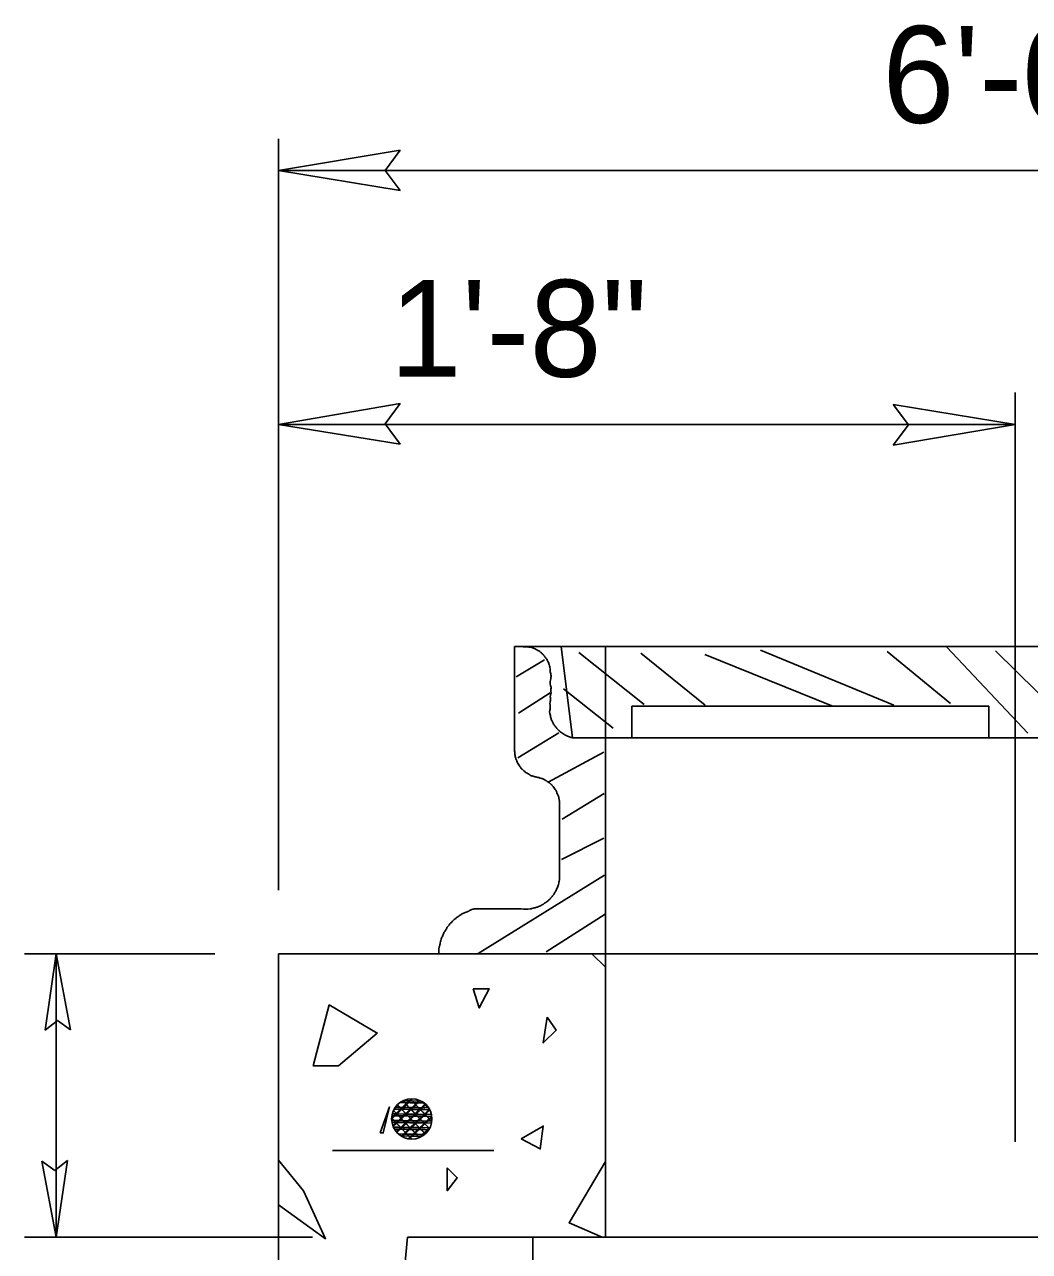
# Model space of a CAD drawing. Extents: x 26.41 to 33.74, y 20.66 to 30.6.
# Drawn here: x 31.629 to 32.251, y 27.649 to 28.409 of the extents above; entities that cross this region are included whole.
import ezdxf

# ---------------------------------------------------------------- set-up
doc = ezdxf.new("R2010")
doc.units = 0
for name, color, linetype in [('DETL-DIMS', 7, 'Continuous'), ('DETL-LINE', 7, 'Continuous'), ('DETL-NOTE', 7, 'Continuous'), ('DETL-PATT', 7, 'Continuous')]:
    doc.layers.add(name, color=color, linetype=linetype)

msp = doc.modelspace()

# ---------------------------------------------------------------- linework, layer by layer
at = {"layer": 'DETL-DIMS'}
for p, q in [((31.7863, 27.87307), (31.7863, 28.33841)), ((31.86177, 28.33142), (31.7863, 28.31876)), ((31.86177, 28.33142), (31.85234, 28.31884)), ((31.86177, 28.30626), (31.7863, 28.31876)), ((31.7863, 28.31876), (33.34406, 28.31876)), ((31.86177, 28.30626), (31.85234, 28.31884)), ((32.24248, 27.71735), (32.24248, 28.18119)), ((31.86173, 28.17447), (31.7863, 28.16154)), ((31.86173, 28.17447), (31.85234, 28.16185)), ((32.16698, 28.17376), (32.24248, 28.16154)), ((32.16698, 28.17376), (32.17645, 28.16122)), ((31.86181, 28.14931), (31.7863, 28.16154)), ((31.7863, 28.16154), (32.24248, 28.16154)), ((31.86181, 28.14931), (31.85234, 28.16185)), ((32.16706, 28.14861), (32.24248, 28.16154)), ((32.16706, 28.14861), (32.17645, 28.16122)), ((31.747, 27.83377), (31.62908, 27.83377)), ((31.64185, 27.78644), (31.64873, 27.83377)), ((31.65758, 27.78676), (31.64873, 27.83377)), ((31.64873, 27.65839), (31.64873, 27.83377)), ((31.64185, 27.78644), (31.64956, 27.7925)), ((31.65758, 27.78676), (31.64956, 27.7925)), ((31.63989, 27.7054), (31.64873, 27.65839)), ((31.63989, 27.7054), (31.64791, 27.69966)), ((31.65561, 27.70571), (31.64791, 27.69966)), ((31.65561, 27.70571), (31.64873, 27.65839)), ((31.80737, 27.65839), (31.62908, 27.65839))]:
    msp.add_line(p, q, dxfattribs=at)
at = {"layer": 'DETL-LINE'}
for p, q in [((32.55233, 28.02397), (31.9326, 28.02397)), ((31.9326, 27.968), (31.9326, 28.02397)), ((31.96848, 27.96753), (31.96133, 28.02397)), ((31.98881, 27.65839), (31.98881, 28.02397)), ((32.0052, 27.98718), (32.0052, 27.96753)), ((32.22629, 27.98718), (32.0052, 27.98718)), ((32.22629, 27.98718), (32.22629, 27.96753)), ((32.51641, 27.96753), (31.96848, 27.96753)), ((31.96047, 27.92622), (31.96047, 27.88094)), ((31.7863, 27.83377), (31.7863, 27.25786)), ((33.34406, 27.83377), (31.7863, 27.83377)), ((31.88579, 27.83377), (32.59918, 27.83377)), ((31.86806, 27.74341), (31.85855, 27.73425)), ((31.86853, 27.74313), (31.85898, 27.73397)), ((31.85819, 27.73613), (31.86735, 27.72658)), ((31.86798, 27.73759), (31.85843, 27.72839)), ((31.86841, 27.73727), (31.8589, 27.72812)), ((31.87278, 27.7344), (31.85953, 27.73464)), ((31.87281, 27.73735), (31.85957, 27.73759)), ((31.87285, 27.73853), (31.85961, 27.73877)), ((31.86114, 27.73896), (31.87034, 27.72945)), ((31.87085, 27.73464), (31.8613, 27.72544)), ((31.87093, 27.74046), (31.86142, 27.73126)), ((31.8714, 27.74014), (31.86185, 27.73098)), ((31.87694, 27.73727), (31.8637, 27.73751)), ((31.87698, 27.73845), (31.86374, 27.73869)), ((31.86401, 27.73602), (31.87321, 27.72646)), ((31.86413, 27.74183), (31.87329, 27.73232)), ((31.8738, 27.73751), (31.86429, 27.72827)), ((31.87427, 27.73719), (31.86468, 27.728)), ((31.86696, 27.73885), (31.87616, 27.72933)), ((31.87678, 27.74038), (31.86727, 27.73114)), ((31.87722, 27.74006), (31.86767, 27.73087)), ((31.86983, 27.73594), (31.87903, 27.72635)), ((31.86995, 27.74171), (31.87914, 27.7322)), ((31.87965, 27.73739), (31.8701, 27.72819)), ((31.88005, 27.73708), (31.87054, 27.72788)), ((31.85808, 27.73028), (31.86723, 27.72076)), ((31.87266, 27.7291), (31.85941, 27.72933)), ((31.8727, 27.73028), (31.85945, 27.73051)), ((31.87274, 27.73322), (31.85949, 27.73346)), ((31.86106, 27.73315), (31.87022, 27.72359)), ((31.87128, 27.73433), (31.86177, 27.72513)), ((31.87678, 27.72902), (31.86354, 27.72925)), ((31.87682, 27.7302), (31.86358, 27.73043)), ((31.87686, 27.73315), (31.86362, 27.73338)), ((31.8769, 27.73433), (31.86366, 27.73456)), ((31.86389, 27.7302), (31.87309, 27.72065)), ((31.87372, 27.73165), (31.86417, 27.72249)), ((31.87415, 27.73134), (31.8646, 27.72214)), ((31.86684, 27.73307), (31.87608, 27.72348)), ((31.87659, 27.72867), (31.86704, 27.71951)), ((31.87667, 27.73452), (31.86715, 27.72532)), ((31.87698, 27.72839), (31.86747, 27.71919)), ((31.8771, 27.73421), (31.86755, 27.72501)), ((31.88091, 27.72894), (31.86767, 27.72918)), ((31.88095, 27.73012), (31.86771, 27.73036)), ((31.88099, 27.73307), (31.86774, 27.7333)), ((31.88103, 27.73425), (31.86778, 27.73448)), ((31.87954, 27.73153), (31.86998, 27.72238)), ((31.87997, 27.73122), (31.87042, 27.72206)), ((31.87258, 27.72497), (31.85933, 27.72521)), ((31.87262, 27.72615), (31.85937, 27.72639)), ((31.87667, 27.72194), (31.86342, 27.72218)), ((31.87671, 27.72489), (31.86346, 27.72513)), ((31.87675, 27.72607), (31.8635, 27.72631)), ((31.91967, 27.71188), (31.81983, 27.71188)), ((31.85811, 27.57172), (31.86633, 27.65839)), ((31.86633, 27.65839), (33.24596, 27.65839)), ((31.94396, 27.25786), (31.94396, 27.65839))]:
    msp.add_line(p, q, dxfattribs=at)
for points in [[(31.86869, 27.74399), (31.86153, 27.73712)], [(31.8694, 27.74399), (31.86197, 27.7368)], [(31.8633, 27.7427), (31.87046, 27.73531)], [(31.87289, 27.74262), (31.86358, 27.74282)], [(31.86881, 27.7427), (31.86358, 27.74282)], [(31.86468, 27.74278), (31.86358, 27.74282)], [(31.8747, 27.74262), (31.86381, 27.74282)], [(31.87364, 27.74309), (31.8644, 27.73413)], [(31.86869, 27.74399), (31.86452, 27.73999)], [(31.87419, 27.74285), (31.8648, 27.73385)], [(31.8694, 27.74399), (31.86491, 27.73967)], [(31.87364, 27.74309), (31.86739, 27.737)], [(31.87419, 27.74285), (31.86778, 27.73668)], [(31.86782, 27.74396), (31.8734, 27.73814)], [(31.86782, 27.74396), (31.87627, 27.73519)], [(31.8747, 27.74262), (31.86794, 27.74274)], [(31.8747, 27.74262), (31.87207, 27.74266)], [(31.87502, 27.74246), (31.87639, 27.74101)], [(31.87502, 27.74246), (31.87926, 27.73806)], [(31.87502, 27.74246), (31.88009, 27.73719)], [(31.86554, 27.74026), (31.85646, 27.73153)], [(31.86256, 27.73739), (31.85646, 27.73153)], [(31.86511, 27.74058), (31.8565, 27.73224)], [(31.86212, 27.73771), (31.8565, 27.73224)], [(31.85918, 27.73484), (31.8565, 27.73224)], [(31.86865, 27.73448), (31.8569, 27.73468)], [(31.86452, 27.73452), (31.8569, 27.73468)], [(31.86039, 27.7346), (31.8569, 27.73468)], [(31.86499, 27.73472), (31.85721, 27.72725)], [(31.8576, 27.73672), (31.86448, 27.72957)], [(31.86869, 27.73743), (31.85808, 27.73763)], [(31.86456, 27.73751), (31.85808, 27.73763)], [(31.86043, 27.73759), (31.85808, 27.73763)], [(31.86873, 27.73857), (31.85878, 27.73877)], [(31.8646, 27.73865), (31.85878, 27.73877)], [(31.86047, 27.73873), (31.85878, 27.73877)], [(31.85996, 27.74018), (31.86747, 27.73244)], [(31.87289, 27.74148), (31.86169, 27.74168)], [(31.86877, 27.74156), (31.86169, 27.74168)], [(31.86464, 27.74164), (31.86169, 27.74168)], [(31.87655, 27.7414), (31.86377, 27.74164)], [(31.88005, 27.73719), (31.86782, 27.73743)], [(31.87934, 27.73837), (31.86786, 27.73861)], [(31.87655, 27.7414), (31.8679, 27.74156)], [(31.87726, 27.74081), (31.87022, 27.73401)], [(31.87765, 27.7405), (31.87065, 27.73374)], [(31.88005, 27.73719), (31.87195, 27.73735)], [(31.87934, 27.73837), (31.87199, 27.73853)], [(31.87655, 27.7414), (31.87203, 27.74148)], [(31.87281, 27.73877), (31.88127, 27.72996)], [(31.87985, 27.73755), (31.87309, 27.73106)], [(31.88009, 27.73712), (31.87352, 27.73075)], [(31.87568, 27.73582), (31.88127, 27.72996)], [(31.8758, 27.74164), (31.88009, 27.73719)], [(31.87863, 27.73865), (31.88009, 27.73719)], [(31.85961, 27.73452), (31.85646, 27.73153)], [(31.85646, 27.73193), (31.86149, 27.7267)], [(31.85646, 27.73193), (31.86436, 27.72371)], [(31.85662, 27.73165), (31.85646, 27.73153)], [(31.86857, 27.73036), (31.8565, 27.73055)], [(31.86444, 27.73043), (31.8565, 27.73055)], [(31.86032, 27.73047), (31.8565, 27.73055)], [(31.86861, 27.7333), (31.85666, 27.7335)], [(31.86448, 27.73338), (31.85666, 27.7335)], [(31.86035, 27.73346), (31.85666, 27.7335)], [(31.86853, 27.72918), (31.85666, 27.72937)], [(31.8644, 27.72925), (31.85666, 27.72937)], [(31.86028, 27.72933), (31.85666, 27.72937)], [(31.86201, 27.73189), (31.85721, 27.72725)], [(31.85906, 27.72902), (31.85721, 27.72725)], [(31.86543, 27.7344), (31.85745, 27.72674)], [(31.86248, 27.73153), (31.85745, 27.72674)], [(31.85949, 27.7287), (31.85745, 27.72674)], [(31.86786, 27.73177), (31.85933, 27.72356)], [(31.86488, 27.7289), (31.85933, 27.72356)], [(31.86829, 27.73146), (31.85969, 27.72316)], [(31.86531, 27.72863), (31.85969, 27.72316)], [(31.86094, 27.72733), (31.86884, 27.71907)], [(31.87073, 27.72878), (31.86252, 27.72084)], [(31.87116, 27.72851), (31.86299, 27.72061)], [(31.86676, 27.72721), (31.87368, 27.72002)], [(31.86971, 27.73008), (31.87726, 27.72226)], [(31.88111, 27.72894), (31.87179, 27.7291)], [(31.8813, 27.73012), (31.87183, 27.73028)], [(31.8813, 27.73307), (31.87187, 27.73322)], [(31.88111, 27.73425), (31.87191, 27.7344)], [(31.87258, 27.72709), (31.87726, 27.72226)], [(31.8727, 27.73295), (31.87985, 27.72552)], [(31.88127, 27.73319), (31.87297, 27.72525)], [(31.88134, 27.73256), (31.8734, 27.72493)], [(31.87557, 27.72996), (31.87985, 27.72552)], [(31.88127, 27.73319), (31.87596, 27.72808)], [(31.88134, 27.73256), (31.87639, 27.7278)], [(31.87855, 27.73283), (31.88127, 27.72996)], [(31.86849, 27.72623), (31.85756, 27.72642)], [(31.86436, 27.72631), (31.85756, 27.72642)], [(31.86024, 27.72635), (31.85756, 27.72642)], [(31.86845, 27.72505), (31.85819, 27.72525)], [(31.86432, 27.72513), (31.85819, 27.72525)], [(31.8602, 27.72521), (31.85819, 27.72525)], [(31.86193, 27.72603), (31.85933, 27.72356)], [(31.86236, 27.72576), (31.85969, 27.72316)], [(31.87254, 27.72202), (31.86063, 27.72222)], [(31.86841, 27.7221), (31.86063, 27.72222)], [(31.86429, 27.72218), (31.86063, 27.72222)], [(31.8725, 27.72084), (31.86224, 27.72104)], [(31.86837, 27.72092), (31.86224, 27.72104)], [(31.86425, 27.721), (31.86224, 27.72104)], [(31.86774, 27.72591), (31.86252, 27.72084)], [(31.86476, 27.72304), (31.86252, 27.72084)], [(31.86818, 27.72564), (31.86299, 27.72061)], [(31.86523, 27.72277), (31.86299, 27.72061)], [(31.87521, 27.7208), (31.86338, 27.721)], [(31.86381, 27.72434), (31.86884, 27.71907)], [(31.86664, 27.72135), (31.86884, 27.71907)], [(31.8736, 27.7258), (31.86676, 27.71927)], [(31.87061, 27.72293), (31.86676, 27.71927)], [(31.86763, 27.7201), (31.86676, 27.71927)], [(31.87403, 27.72552), (31.86747, 27.71919)], [(31.87105, 27.72265), (31.86747, 27.71919)], [(31.8681, 27.71978), (31.86747, 27.71919)], [(31.87521, 27.7208), (31.86751, 27.72092)], [(31.87686, 27.72194), (31.86755, 27.7221)], [(31.87942, 27.72485), (31.86759, 27.72505)], [(31.88009, 27.72599), (31.86763, 27.72623)], [(31.86963, 27.72422), (31.87368, 27.72002)], [(31.87521, 27.7208), (31.87164, 27.72084)], [(31.87686, 27.72194), (31.87167, 27.72202)], [(31.87942, 27.72485), (31.87171, 27.72497)], [(31.88009, 27.72599), (31.87175, 27.72615)], [(31.8725, 27.72124), (31.87368, 27.72002)], [(31.8804, 27.72666), (31.87337, 27.7199)], [(31.87946, 27.72572), (31.87337, 27.7199)], [(31.87647, 27.72285), (31.87337, 27.7199)], [(31.87348, 27.71998), (31.87337, 27.7199)], [(31.87973, 27.72529), (31.87478, 27.72053)], [(31.87973, 27.72529), (31.87478, 27.72053)], [(31.87686, 27.72253), (31.87478, 27.72053)], [(31.87545, 27.72411), (31.87726, 27.72226)], [(31.8804, 27.72666), (31.87584, 27.72226)], [(31.87973, 27.72529), (31.87627, 27.72194)], [(31.87844, 27.72698), (31.87985, 27.72552)], [(31.8804, 27.72666), (31.87883, 27.72513)], [(31.87973, 27.72529), (31.87926, 27.72481)]]:
    msp.add_lwpolyline(points, dxfattribs=at)
msp.add_circle((31.86892, 27.73153), 0.01249, dxfattribs=at)
for points in [[(31.9326, 28.02397), (31.93967, 28.02381), (31.94317, 28.02334), (31.94529, 28.02251), (31.94636, 28.022), (31.94753, 28.02126), (31.94875, 28.02039), (31.94958, 28.01961), (31.95013, 28.01909), (31.9504, 28.0189), (31.95072, 28.01843), (31.95119, 28.01795), (31.95158, 28.0174), (31.95198, 28.01685), (31.95253, 28.01611), (31.95296, 28.01516), (31.95323, 28.01465), (31.95371, 28.01351), (31.95418, 28.0121), (31.95441, 28.01096), (31.95465, 28.00958), (31.95465, 28.00832), (31.955, 28.00707), (31.95508, 28.00483), (31.95477, 28.00322), (31.95489, 27.9998), (31.9552, 27.99885), (31.95496, 27.99752), (31.95508, 27.99469), (31.95473, 27.99374), (31.95485, 27.99056), (31.95453, 27.98958), (31.95465, 27.98576), (31.95437, 27.98451), (31.95441, 27.98258), (31.95477, 27.98132), (31.95489, 27.98046), (31.95555, 27.9783), (31.9565, 27.97657), (31.95701, 27.9755), (31.95768, 27.97472), (31.95842, 27.97362), (31.95913, 27.97287), (31.95968, 27.97228), (31.96015, 27.97193), (31.96058, 27.97146), (31.96113, 27.97091), (31.96239, 27.97012), (31.96361, 27.96937), (31.96416, 27.96906), (31.96463, 27.96886), (31.96538, 27.96847), (31.96656, 27.968), (31.96848, 27.96753)], [(31.9326, 27.968), (31.9326, 27.96666), (31.93256, 27.96556), (31.9326, 27.96481), (31.93248, 27.96379), (31.93248, 27.96257), (31.93248, 27.96171), (31.93248, 27.95994), (31.93256, 27.95923), (31.93268, 27.95817), (31.9328, 27.95719), (31.93299, 27.95585), (31.93327, 27.95479), (31.9335, 27.95404), (31.93374, 27.95357), (31.93397, 27.95294), (31.93445, 27.95192), (31.93515, 27.9507), (31.9359, 27.94968), (31.93653, 27.94878), (31.93732, 27.94799), (31.93787, 27.9474), (31.9383, 27.94709), (31.93971, 27.94591), (31.94089, 27.94524), (31.94195, 27.94461), (31.94246, 27.94426), (31.94349, 27.9439), (31.94415, 27.94367), (31.94506, 27.94339), (31.94624, 27.94316), (31.94757, 27.94284), (31.94926, 27.94233), (31.95001, 27.94206), (31.95052, 27.94182), (31.95111, 27.94154), (31.95158, 27.94127), (31.95213, 27.94099), (31.95284, 27.94048), (31.95351, 27.94001), (31.9541, 27.93954), (31.95489, 27.93891), (31.95555, 27.93828), (31.95591, 27.93789), (31.95697, 27.93667), (31.95775, 27.93545), (31.95827, 27.93463), (31.95866, 27.93392), (31.95901, 27.9329), (31.95944, 27.93211), (31.95968, 27.93144), (31.95988, 27.9307), (31.96007, 27.92999), (31.96027, 27.92889), (31.96039, 27.92794), (31.96039, 27.92688), (31.96047, 27.92622)], [(31.96047, 27.88094), (31.96007, 27.87814), (31.95972, 27.87677), (31.95933, 27.87547), (31.95882, 27.87421), (31.95827, 27.87307), (31.95779, 27.87221), (31.95732, 27.87142), (31.95681, 27.87056), (31.95614, 27.86969), (31.95559, 27.86899), (31.95489, 27.8682), (31.95418, 27.86737), (31.95363, 27.8669), (31.95308, 27.86643), (31.95253, 27.866), (31.95178, 27.86541), (31.95119, 27.86506), (31.95048, 27.86458), (31.95001, 27.86427), (31.94899, 27.86372), (31.94805, 27.86329), (31.94679, 27.86274), (31.94474, 27.86215), (31.94333, 27.86183), (31.94227, 27.86156), (31.93657, 27.8616), (31.93507, 27.86168), (31.93378, 27.86168), (31.93083, 27.86168), (31.92938, 27.86168), (31.92824, 27.86168), (31.92686, 27.86168), (31.92368, 27.86168), (31.92187, 27.86168), (31.91908, 27.86168), (31.91786, 27.86168), (31.91637, 27.86168), (31.9144, 27.86168), (31.91361, 27.86168), (31.91287, 27.86168), (31.91126, 27.86168), (31.91027, 27.86168), (31.90815, 27.86164), (31.90619, 27.86113), (31.90422, 27.86026), (31.90206, 27.85936), (31.90096, 27.85896), (31.90017, 27.85849), (31.89958, 27.85822), (31.89891, 27.85771), (31.89801, 27.85716), (31.89734, 27.85672), (31.89648, 27.85602), (31.89569, 27.85539), (31.89475, 27.8546), (31.89412, 27.85397), (31.89314, 27.85287), (31.89255, 27.85224), (31.89227, 27.85201), (31.89196, 27.85157), (31.8916, 27.85114), (31.89129, 27.85075), (31.8909, 27.85028), (31.89054, 27.84957), (31.89027, 27.84894), (31.88976, 27.84827), (31.88932, 27.8476), (31.88877, 27.8467), (31.88838, 27.84568), (31.88736, 27.84344), (31.88657, 27.84065), (31.88586, 27.83778), (31.88579, 27.83377)]]:
    msp.add_spline(points, degree=3, dxfattribs=at)
at = {"layer": 'DETL-PATT'}
for p, q in [((32.2505, 27.97047), (32.20023, 28.02369)), ((32.01274, 27.98808), (31.97234, 28.02035)), ((32.05055, 27.98769), (32.01078, 28.01992)), ((32.12897, 27.98726), (32.05048, 28.01913)), ((32.16745, 27.98777), (32.08487, 28.02169)), ((32.20243, 27.98871), (32.16332, 28.02086)), ((32.26961, 27.98266), (32.23038, 28.02126)), ((31.95115, 28.01568), (31.93362, 28.00522)), ((31.93504, 27.98274), (31.95457, 27.99539)), ((31.99356, 27.97338), (31.96282, 27.99775)), ((31.96003, 27.97055), (31.93464, 27.95507)), ((31.95335, 27.94009), (31.98778, 27.95864)), ((31.98806, 27.93298), (31.962, 27.91706)), ((31.96168, 27.8921), (31.98774, 27.90527)), ((31.98833, 27.88243), (31.90992, 27.834)), ((31.95221, 27.83507), (31.98865, 27.85837))]:
    msp.add_line(p, q, dxfattribs=at)
for points in [[(31.98881, 27.8254), (31.98047, 27.83377)], [(31.7863, 27.67824), (31.81543, 27.65733), (31.80175, 27.68704), (31.7863, 27.70606)], [(31.9868, 27.65839), (31.96636, 27.66723), (31.98881, 27.70524)]]:
    msp.add_lwpolyline(points, dxfattribs=at)
for points in [[(31.90693, 27.81203), (31.91071, 27.80024), (31.91684, 27.81203)], [(31.82345, 27.76439), (31.8475, 27.78468), (31.81779, 27.80213), (31.80788, 27.76439)], [(31.95268, 27.79458), (31.95033, 27.77854), (31.95834, 27.78656)], [(31.84939, 27.72289), (31.85128, 27.72289), (31.85505, 27.73892)], [(31.93665, 27.71911), (31.94844, 27.71298), (31.95033, 27.72713)], [(31.8909, 27.70119), (31.8909, 27.68704), (31.89703, 27.69506)]]:
    msp.add_lwpolyline(points, close=True, dxfattribs=at)

# ---------------------------------------------------------------- texts
at = {"layer": 'DETL-NOTE'}
for s, p in [('6\'-0"', (32.16037, 28.34824)), ('1\'-8"', (31.85521, 28.19102))]:
    msp.add_text(s, height=0.05998, dxfattribs=at).set_placement(p)

doc.saveas('drawing.dxf')
